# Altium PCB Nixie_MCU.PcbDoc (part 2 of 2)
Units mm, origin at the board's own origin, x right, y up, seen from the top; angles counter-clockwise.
Board outline 188 x 42 mm, 4 copper layers (Signal Layer 1, Layer 1, Layer 2, Bottom Layer), stack 1.466 mm thick; 180 components, 100 nets, 460 pads, 258 vias.
Unrouted connection lines stored in the file: 2.
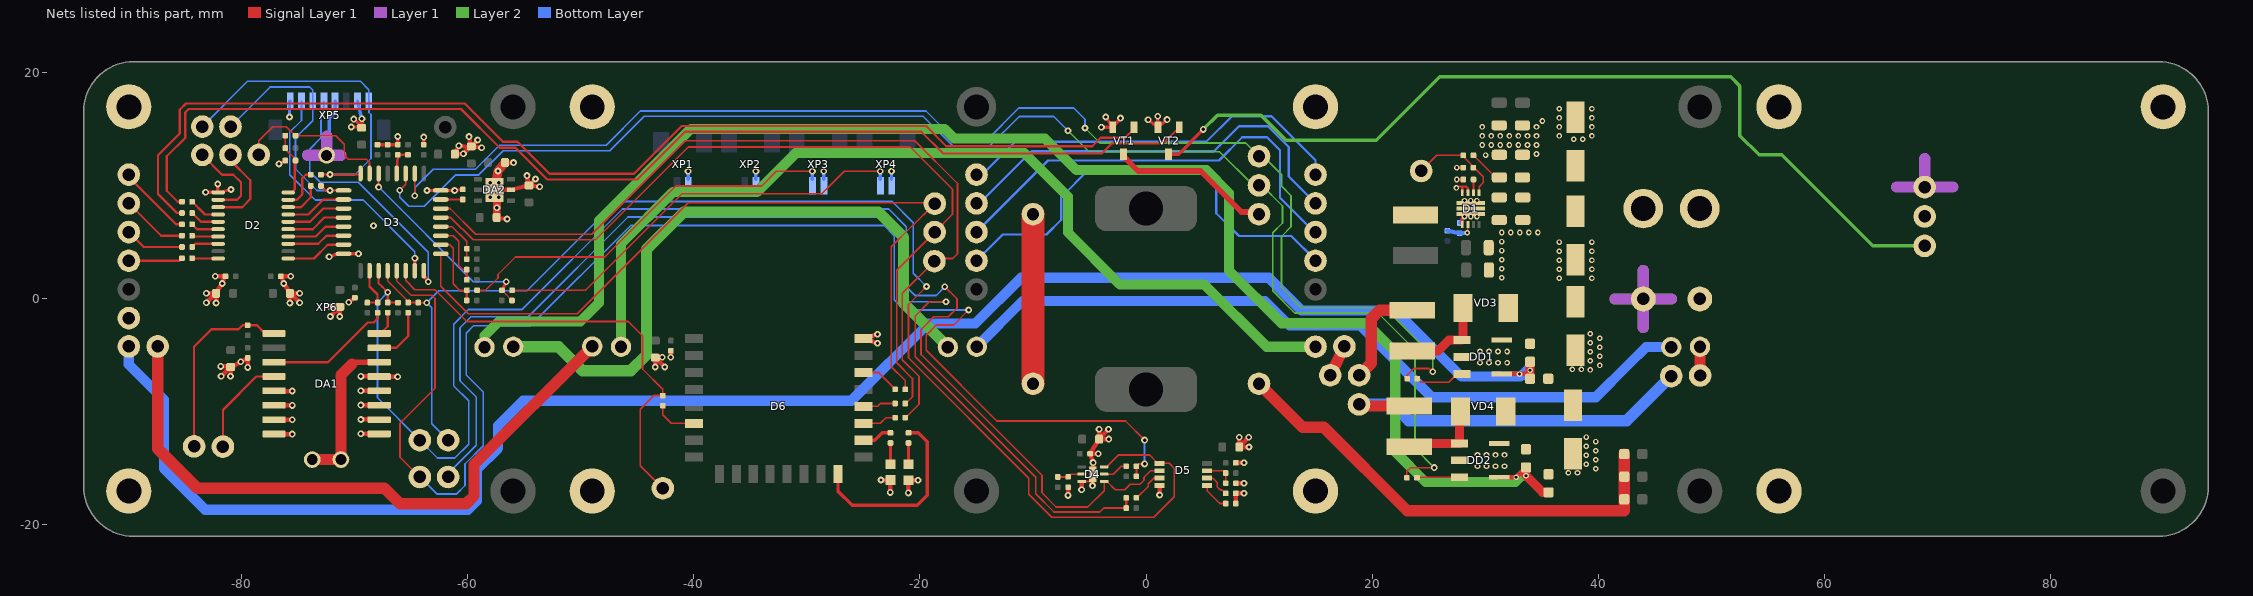
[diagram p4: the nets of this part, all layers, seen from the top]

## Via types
v1: diameter 0.6, hole 0.3, Signal Layer 1 to Bottom Layer, tented both sides, 153 vias
v2: diameter 0.5, hole 0.25, Signal Layer 1 to Bottom Layer, tented both sides, 101 vias
v3: diameter 0.6, hole 0.3, Signal Layer 1 to Bottom Layer, 4 vias

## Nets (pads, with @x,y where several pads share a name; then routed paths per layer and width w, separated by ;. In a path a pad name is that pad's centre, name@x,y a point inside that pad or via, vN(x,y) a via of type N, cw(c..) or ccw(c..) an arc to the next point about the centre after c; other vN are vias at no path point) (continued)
BTN_3: R38.1 XP3.1 | length 34.9
  Signal Layer 1 w0.15: R38.1@-59.189,0.766 -58.434,0.766 -57.341,1.859 -57.341,2.159 -55.783,3.717 -47.891,3.717 -41.607,10 -34,10 -32.701,11.299 v1(-29.515,11.299)
  Bottom Layer w0.3: XP3.1@-29.515,10.578 v1(-29.515,11.299)
BTN_4: R45.1 XP4.1 | length 37.7
  Signal Layer 1 w0.15: R45.1@-56.087,0.772 -55.228,0.772 -49.59,0.772 -41.05,9.311 -28.689,9.311 -26.701,11.299 v1(-23.515,11.299)
  Bottom Layer w0.3: XP4.1@-23.515,10.578 v1(-23.515,11.299)
DIMM_LED_1: D3.2 R5.1 XS41.1 | length 118.3
  Signal Layer 1 w0.15: v1(-64.708,9.13) -64.7,9.75 D3.2@-64.7,11.1 ; R5.1@23.1,-7.05 23.1,-6.75 23.7,-6.15 25.075,-6.15 v1(25.375,-6.45)
  Layer 2 w0.15: v1(-5.4,15.125) -4.075,13.8 8.825,13.8 XS41.1@10,12.625 10.375,12.625 12,11 12,9.958 12.828,9.129 12.828,6.377 11.983,5.532 11.983,0.984 13.751,-0.784 21.111,-0.784 25.375,-5.048 v1(25.375,-6.45)
  Bottom Layer w0.15: v1(-64.708,9.13) -64.708,9.842 -63.075,11.475 -59.325,11.475 -57.2,13.6 -47.761,13.6 -44.734,16.626 -19.471,16.626 -16.944,14.1 -14.05,14.1 -11.25,16.9 -6.4,16.9 -5.4,15.9 v1(-5.4,15.125)
DIMM_LED_2: D3.3 R57.1 XS62.1 | length 126.4
  Signal Layer 1 w0.15: v1(-66.025,9.625) -65.5,10.15 D3.3@-65.5,11.1 ; R57.1@23.075,-15.825 23.075,-15.25 23.4,-14.925 v1(25.5,-14.925)
  Layer 2 w0.15: v1(-6.9,14.875) -5.05,13.025 6.5,13.025 9.475,10.05 XS62.1@10,10.05 10.256,10.05 12.076,8.23 12.076,6.717 11.209,5.849 11.209,0.716 13.17,-1.245 20.53,-1.245 23.798,-4.513 23.798,-13.223 v1(25.5,-14.925)
  Bottom Layer w0.15: v1(-66.025,9.625) -66.025,9 -65.225,8.2 -63.85,8.2 -61.075,10.975 -59.025,10.975 -56.875,13.125 -47.45,13.125 -44.399,16.176 -19.726,16.176 -17.05,13.5 -13.875,13.5 -11.225,16.15 -8.175,16.15 v1(-6.9,14.875)
DIN: XS30.1 XS36.1 | length 35
  Bottom Layer w0.2: XS30.1@-15,11 -14.5,11 -11.6,13.9 5.325,13.9 7.6,16.175 11.094,16.175 15,12.269 XS36.1@15,11
DIN_3.3V: D2.5 D3.12 | length 5.3
  Signal Layer 1 w0.2: D2.5@-75.9,6.175 -73.725,6.175 -72.7,7.2 D3.12@-71,7.2
DIN_5V: R10.2 XS6.1 | length 6.7
  Signal Layer 1 w0.2: XS6.1@-90,11 -90,10.781 -85.819,6.6 R10.2@-85.3,6.6
EN_VCC3.3: D1.8 R1.1 R2.2 XS51.1 | length 8.5
  Signal Layer 1 w0.15: XS51.1@24.35,11.325 25.729,12.704 R2.2@28.073,12.704 28.073,12.602 29.85,10.825 29.85,10.31 29.477,9.937 D1.8@29.477,9.4
GND: C1.1 C2.1 C3.1 C4.1 C5.2 C6.2 C7.2 C8.1 C9.1 C10.1 C11.1 C12.1 C13.1 C14.1 C15.1 C16.1 C17.1 C18.1 C19.1 C20.1 C21.1 C22.1 C23.1 C24.1 C25.1 C26.1 C27.1 C28.1 C29.1 C30.1 C31.1 C32.1 C33.1 C34.1 C35.1 C36.1 C37.2 D1.3 D1.4 D1.10 D1.11 D2.11 D3.16 D3.32 D4.3 D4.7 D5.4 D6.24 DA1.5 DA1.6 DA1.7 DA1.8 DA1.9 DA1.10 DA1.11 DA1.12 DA1.13 DA2.2 DA2.7 DD1.2 DD2.2 pad.16@15,17 pad.16@15,-17 pad.16@44,8 pad.16@56,17 pad.16@56,-17 pad.16@-49,17 pad.16@-49,-17 pad.16@-90,17 pad.16@-90,-17 R1.2 R3.2 R6.1 R18.2 R28.1 R31.2 R32.2 R33.2 VD1.2 VD2.2 VT1.2 VT2.2 XP1.2 XP2.2 XP3.2 XP4.2 XP5.1 XP5.5 XP5.7 XP6.2 XS2.1 XS8.1 XS23.1 | length 138.3
  Signal Layer 1 w0.2: D4.3@-5.695,-16.15 -5.014,-16.15 D4.7@-4.729,-15.865 ; v2(27.464,9.828) 27.586,9.95 27.977,9.95 ; D1.11@27.977,9.4 27.977,9.95 ; D1.10@28.477,9.4 28.477,9.792 28.319,9.95 27.977,9.95
  Signal Layer 1 w0.25: v2(27.496,11.624) R1.2@28.07,11.624 ; v2(27.499,10.568) C3.1@28.073,10.568 ; D1.4@27.97,6.606 27.97,7.094 v2(28.177,7.3)
  Signal Layer 1 w0.3: v1(-83.206,9.437) D2.11@-82.485,9.437 ; v1(-82.134,10.171) -82.134,9.45 D2.11@-82.105,9.42 ; D2.11@-82.1,9.425 v1(-80.963,9.683) ; v1(-76.71,11.952) -76.25,12.19 R6.1@-76.15,12.25 ; v1(-72.277,3.729) D3.16@-71.5,4 ; D3.16@-70.4,4 v1(-69.679,4) ; v1(-70.313,15.21) C19.1@-69.592,15.21 ; v1(-70.089,15.913) C19.1@-69.391,15.304 ; v1(-69.378,15.94) C19.1@-69.313,15.202 ; C18.1@-68,13.65 C17.1@-67.1,13.65 C14.1@-66.379,13.65 ; C14.1@-66.2,13.65 v1(-66.2,14.371) ; C15.1@-63.907,13.648 v1(-63.896,14.325) ; v1(-63.621,9.6) D3.32@-62.9,9.6 ; D3.32@-61.9,9.6 v1(-61.179,9.6) R18.2@-60.456,9.703 ; v1(-3.943,15.197) VT1.2@-2.95,15.2 ; v1(-3.564,16.101) VT1.2@-2.95,15.2 ; v1(-2.26,16.002) VT1.2@-2.95,15.2 ; v1(0.185,15.859) VT2.2@1.05,15.2 ; v1(1.049,16.166) VT2.2@1.05,15.2 ; v1(1.867,15.866) VT2.2@1.05,15.2
  Signal Layer 1 w0.4: v1(-83.137,-0.333) -82.304,0.5 v1(-83.137,0.5) ; v1(-82.362,2) -81.529,2 v1(-81.737,1.368) C12.1@-82.275,0.5 v1(-82.275,-0.362) ; v1(-81.862,-5.971) C21.1@-81,-5.971 ; v1(-81.833,-6.833) -81,-6 v1(-81,-6.833) ; C21.1@-80.691,-5.909 v1(-80.088,-5.565) C20.1@-79.485,-5.222 v1(-79.485,-6.055) ; DA1.8@-76.365,-11.958 v1(-75.532,-11.958) ; DA1.7@-76.365,-10.688 v1(-75.532,-10.688) ; DA1.6@-76.365,-9.418 v1(-75.532,-9.418) ; DA1.5@-76.365,-8.148 v1(-75.532,-8.148) ; v1(-75.75,-0.362) C9.1@-75.75,0.5 v1(-76.288,1.368) -76.496,2 v1(-75.663,2) ; v1(-74.888,-0.333) -75.721,0.5 v1(-74.888,0.5) ; v1(-72.196,-0.695) C16.1@-71.334,-0.695 ; v1(-72.167,-1.557) -71.334,-0.724 v1(-71.334,-1.557) ; v1(-70.547,-0.285) C13.1@-69.994,0.109 ; v1(-69.468,-11.932) DA1.9@-68.635,-11.932 ; v1(-69.468,-10.662) DA1.10@-68.635,-10.662 ; v1(-69.468,-9.392) DA1.11@-68.635,-9.392 ; v1(-69.468,-8.122) DA1.12@-68.635,-8.122 ; v1(-69.468,-6.852) DA1.13@-68.635,-6.852 ; DA1.13@-67.055,-6.878 v1(-66.222,-6.878) ; C26.1@-61.178,12.82 -61.172,12.831 v1(-60.796,13.555) C30.1@-59.879,13.429 ; C26.1@-61.149,12.82 v1(-60.398,12.839) C30.1@-59.84,13.405 ; v1(-59.901,14.362) C30.1@-59.729,13.5 ; v1(-59.142,14.066) C30.1@-59.7,13.5 v1(-58.783,13.374) ; DA2.7@-57.647,9.642 DA2.2@-56.197,9.642 C27.1@-54.6,10.05 v1(-54.772,10.912) ; C28.1@-57.479,7.2 -57.479,7.201 -57.451,7.734 v1(-57.434,8.074) ; C28.1@-57.45,7.2 v1(-56.533,7.074) ; C29.1@-56.723,12.073 v1(-55.966,12.064) ; v1(-54.013,10.616) -54.571,10.05 v1(-53.654,9.924) ; v1(-43.416,-6.024) C31.1@-43.416,-5.19 ; v1(-42.808,-5.156) -43.382,-5.156 C31.1@-43.416,-5.19 ; v1(-42.583,-6.024) C31.1@-43.416,-5.19 ; v1(-42.047,-5.148) C32.1@-42.04,-4.579 ; v1(-23.753,-3.916) -24.993,-3.522 v1(-23.753,-3.127) ; v1(-23.444,-16.021) VD1.2@-22.61,-16.021 ; v1(-22.637,-17.12) VD1.2@-22.637,-16.287 ; v1(-21.023,-17.164) VD2.2@-21.023,-16.33 ; VD2.2@-21.011,-16.036 v1(-20.178,-16.036) ; v1(-6.898,-17.381) R28.1@-6.895,-16.646 ; v1(-5.698,-16.884) D4.3@-5.695,-16.232 ; v1(-4.732,-16.518) D4.7@-4.729,-15.865 ; D4.7@-4.681,-15.128 v1(-4.678,-14.476) C24.1@-4.95,-13.7 ; v1(-4.216,-13.703) C24.1@-4.95,-13.7 ; v1(-4.15,-11.538) -4.15,-12.371 v1(-3.317,-11.538) ; v1(-3.288,-12.4) C22.1@-4.15,-12.4 C24.1@-4.95,-13.7 ; v1(1.2,-17.35) D5.4@1.2,-16.627 ; R33.2@7.95,-18.1 R32.2@7.95,-17.377 ; R32.2@7.95,-17.2 v1(8.673,-17.2) ; R31.2@7.95,-16.3 v1(8.673,-16.3) ; C25.1@7.95,-14.5 v1(8.673,-14.5) ; C23.1@8.25,-13.1 v1(9.112,-13.1) ; v1(8.25,-12.238) 8.25,-13.071 v1(9.083,-12.238)
  Signal Layer 1 w0.7: C28.1@-57.45,7.2 -57.446,7.77 v1(-57.434,8.074) -57.439,9.004 -57.439,9.008 DA2.7@-57.438,9.067
  Signal Layer 1 w0.8: DA2.7@-57.647,9.642 -57.545,10.187 -57.519,10.325 v1(-57.333,11.32) C29.1@-56.723,12.073
  Layer 1 w1: -74.187,12.713 -74.184,12.71 XP6.2@-72.5,12.71 ; -72.5,14.394 XP6.2@-72.5,12.71 ; -71.249,12.71 XP6.2@-72.5,12.71 ; 41.5,0 XS2.1@44,0 ; 44,-2.5 XS2.1@44,0 ; 44,2.5 XS2.1@44,0 ; 46.5,0 XS2.1@44,0 ; 66.4,9.9 XS23.1@68.9,9.9 ; 68.9,12.4 XS23.1@68.9,9.9 ; 71.4,9.9 XS23.1@68.9,9.9
  Layer 2 w1: 41.5,0 XS2.1@44,0 ; 44,-2.5 XS2.1@44,0 ; 44,2.5 XS2.1@44,0 ; 46.5,0 XS2.1@44,0
  Bottom Layer w0.3: v1(-75.785,16.1) -75.785,17.441 XP5.1@-75.726,17.5 ; XP6.2@-72.5,12.71 -72.25,12.96 -72.25,15.971 -71.75,16.471 XP5.5@-71.75,17.5 ; XP5.7@-69.766,17.5 v1(-69.378,15.94) ; XP1.2@-40.515,10.578 v1(-40.515,11.299) ; XP2.2@-34.515,10.578 v1(-34.515,11.299) ; XP3.2@-28.515,10.578 v1(-28.515,11.299) ; XP4.2@-22.515,10.578 v1(-22.515,11.299) ; R3.2@27.75,6.725 v2(28.177,7.3)
  other v1: -68.354,6.477
  other v2: 37.376,-15.38 38.176,-15.38 39.8,-15.025 29.325,-14.8 30.125,-14.8 30.925,-14.8 31.725,-14.8 38.95,-14.625 39.8,-14.225 38.95,-13.825 29.325,-13.8 30.125,-13.8 30.925,-13.8 31.725,-13.8 39.8,-13.425 38.95,-13.025 39.8,-12.625 38.95,-12.225 39.3,-6.275 37.726,-6.23 38.526,-6.23 40.15,-5.875 29.55,-5.65 30.35,-5.65 31.15,-5.65 31.95,-5.65 39.3,-5.475 40.15,-5.075 39.3,-4.675 29.55,-4.65 30.35,-4.65 31.15,-4.65 31.95,-4.65 40.15,-4.275 39.3,-3.875 40.15,-3.475 39.3,-3.075 36.57,1.826 39.45,1.826 31.475,1.875 36.57,2.626 39.45,2.626 31.475,2.675 36.57,3.426 39.45,3.426 31.475,3.475 36.57,4.226 39.45,4.226 31.475,4.275 36.57,5.026 39.45,5.026 31.475,5.075 31.475,5.875 32.275,5.875 33.075,5.875 33.875,5.875 34.675,5.875 28.727,7.3 29.277,7.3 30.05,12.725 34.55,12.825 29.75,13.625 30.55,13.625 31.35,13.625 32.15,13.625 32.95,13.625 33.75,13.625 34.55,13.625 37.85,14.125 38.65,14.125 29.75,14.425 30.55,14.425 31.35,14.425 32.15,14.425 32.95,14.425 33.75,14.425 34.55,14.425 36.57,14.425 39.45,14.425 29.75,15.225 34.55,15.225 36.57,15.225 39.45,15.225 35.075,15.75 36.57,16.025 39.45,16.025 36.57,16.825 39.45,16.825
  other v3: -58.028,9.007 -57.266,9.007 -58.028,10.277 -57.266,10.277
I2C_SCL: D3.19 D4.4 D5.2 R13.2 R15.1 XS43.1 | length 128.6
  Signal Layer 1 w0.15: v1(-17.8,1.075) -16.715,-0.01 -16.715,-0.796 -17.503,-1.584 -18.779,-1.584 -19.91,-2.715 -19.91,-4.908 -9.205,-15.612 -9.205,-17.159 -7.958,-18.406 -5.156,-18.406 -3.705,-16.955 D4.4@-3.705,-16.15 -3.45,-16.15 -2.721,-16.879 -1.879,-16.879 -1.391,-16.391 -0.534,-16.391 -0.172,-16.029 -0.172,-15.772 0.4,-15.2 D5.2@1.2,-15.2
  Signal Layer 1 w0.2: D3.19@-67.9,2.5 -67.9,1.4 -67.583,1.083 -67.146,0.646 v1(-67.088,0.588) ; R15.1@-67.088,-0.314 v1(-67.088,0.588) ; R15.1@-67.013,-0.324 R13.2@-66.187,-0.324
  Bottom Layer w0.15: v1(-67.088,0.588) -67.942,-0.265 ccw(c-67.8,-0.406) -68,-0.406 -68,-8.75 XS43.1@-64.25,-12.5 -62.682,-14.068 -61.159,-14.068 -59.933,-12.842 -59.933,-9.017 -61.252,-7.698 -61.252,-2.227 -59.95,-0.925 -55.2,-0.925 -46.32,7.955 -22.762,7.955 -21.206,6.398 -21.206,1.073 -20.431,0.298 -18.577,0.298 v1(-17.8,1.075)
I2C_SDA: D3.20 D4.6 D5.1 R12.2 R16.1 XS42.1 | length 119.5
  Signal Layer 1 w0.15: D3.20@-67.1,2.5 -67.1,1.589 -65.334,-0.177 -65.287,-0.177 -65.141,-0.176 R16.1@-65.286,-0.318 R12.2@-64.389,-0.318 ; R12.2@-64.533,-0.343 v1(-63.636,-0.343) ; v1(-19.425,1.1) -21.011,-0.486 -21.011,-5.201 -10.362,-15.85 -10.362,-17.275 -8.33,-19.306 0.694,-19.306 2.5,-17.5 2.5,-15 2.05,-14.55 D5.1@1.2,-14.55 ; D4.6@-3.705,-14.85 -3.473,-14.85 -2.423,-13.8 0.308,-13.8 D5.1@0.978,-14.47
  Bottom Layer w0.15: XS42.1@-61.75,-12.5 -63.207,-11.043 -63.207,-0.771 v1(-63.636,-0.343) -62.568,0.725 -54.77,0.725 -46.876,8.619 -22.465,8.619 -20.603,6.757 -20.603,2.278 v1(-19.425,1.1)
I\N\T\\/SQW: D3.18 R11.2 R17.1 | length 4
  Signal Layer 1 w0.2: R11.2@-68.891,-0.32 -67.992,-0.32 R17.1@-67.988,-0.316 -67.988,0.388 -68.7,1.1 D3.18@-68.7,2.5
INS_EN_3.3V: D2.6 D3.11 | length 5.4
  Signal Layer 1 w0.2: D2.6@-75.9,6.825 -73.975,6.825 -72.8,8 D3.11@-71,8
INS_EN_5V: D2.15 R23.2 | length 2.6
  Signal Layer 1 w0.2: R23.2@-84.395,7.603 -83.618,6.825 D2.15@-82.1,6.825
INT_OPT: D3.21 R34.2 R36.1 XS44.1 | length 129.7
  Signal Layer 1 w0.15: D3.21@-66.3,2.5 -66.3,1.595 -65.037,0.332 -63.198,0.332 -62.905,0.038 -62.905,-7.905 -66,-11 -66,-14 XS44.1@-64.25,-15.75 ; v1(-15.7,-0.975) -17.025,-2.3 -18.55,-2.3 -19.45,-3.2 -19.45,-4.55 -13.2,-10.8 -1.809,-10.8 v1(-0.122,-12.487)
  Signal Layer 1 w0.2: R36.1@-0.85,-15.7 R34.2@-0.85,-14.8 -0.647,-14.597 v1(-0.123,-14.597)
  Bottom Layer w0.15: XS44.1@-64.25,-15.75 -62.75,-17.25 -61,-17.25 -60.25,-16.5 -60.25,-14.6 -58.644,-12.994 -58.644,-8.231 -60.15,-6.725 -60.15,-3.025 -59.5,-2.375 -54.479,-2.375 -45.602,6.502 -23.185,6.502 -22.282,5.599 -22.282,-0.068 -21.375,-0.975 v1(-15.7,-0.975)
  Bottom Layer w0.2: v1(-0.123,-14.597) v1@-0.123,-12.488
JDY_PWRC: D3.25 R50.1 XS47.1 | length 70.2
  Signal Layer 1 w0.15: D3.25@-62.4,4 -62.4,1.133 -59.957,-1.31 -50.31,-1.31 -40.489,8.511 -18.758,8.511 XS47.1@-18.686,8.438 -20.72,6.404 -20.746,6.404 -22.532,4.618 -22.532,-5.992 -21.306,-7.219 R50.1@-21.306,-7.994
JDY_STAT: D3.22 R49.1 XS48.1 | length 40.2
  Signal Layer 1 w0.15: D3.22@-65.5,2.5 -65.5,1.64 -64.687,0.827 -62.924,0.827 -62.621,0.524 -60.097,-2 -45.8,-2 -44.55,-3.25 -44.55,-6.2 -42.75,-8 R49.1@-42.75,-8.55 -43.55,-8.55 -44.75,-9.75 -44.75,-14.75 XS48.1@-42.75,-16.75
NetC3_2: C3.2 D1.9 | length 1.2
  Signal Layer 1 w0.2: C3.2@28.973,10.568 28.977,10.418 28.977,9.795 cw(c28.477,9.792) 28.977,9.792 D1.9@28.977,9.4
NetC14_2: C14.2 D3.4 R19.2 | length 2.6
  Signal Layer 1 w0.2: D3.4@-66.3,11.1 C14.2@-66.2,12.75 R19.2@-65.3,12.75
NetD1_2: D1.2 L1.1
NetD1_5: D1.5 R3.1 R4.2 | length 2.5
  Signal Layer 1 w0.15: v2(28.427,5.861) 28.468,6.375 D1.5@28.477,6.6
  Bottom Layer w0.4: R4.2@26.675,6.025 R3.1@27.75,5.825 v2(28.427,5.861)
NetD2_16: D2.16 R10.1 | length 2.5
  Signal Layer 1 w0.2: R10.1@-84.4,6.6 -83.975,6.175 D2.16@-82.1,6.175
NetD2_17: D2.17 R9.1 | length 2.3
  Signal Layer 1 w0.2: R9.1@-84.4,5.6 -84.325,5.525 D2.17@-82.1,5.525
NetD2_18: D2.18 R8.1 | length 2.4
  Signal Layer 1 w0.2: R8.1@-84.4,4.6 -84.125,4.875 D2.18@-82.1,4.875
NetD2_20: D2.20 R7.1 | length 2.3
  Signal Layer 1 w0.2: R7.1@-84.4,3.6 -84.375,3.575 D2.20@-82.1,3.575
NetD3_6: D3.6 R41.2 R45.2 | length 18.1
  Signal Layer 1 w0.15: R45.2@-56.987,0.772 -56.987,0.755 R41.2@-56.099,-0.132
  Signal Layer 1 w0.2: v1@-67.9,9.916 D3.6@-67.9,11.1
  Signal Layer 1 w0.3: R45.2@-56.987,0.772 -56.599,1.511 v1(-56.603,1.518)
  Bottom Layer w0.15: v1(-67.9,9.9) -59.518,1.518 v1(-56.603,1.518)
NetD3_7: D3.7 R46.2 XS46.1 | length 14.4
  Signal Layer 1 w0.15: XS46.1@-78.5,12.75 -78.5,14 -77.25,15.25 -76.056,15.25 R46.2@-75.258,14.453 ; R46.2@-75.25,14.453 -71.703,14.453 -70.943,13.693 -70.943,12.714 -70.59,12.361 -68.968,12.361 -68.7,12.093 D3.7@-68.7,11.1
NetD3_26: D3.26 R38.2 R42.2 | length 6.7
  Signal Layer 1 w0.15: D3.26@-62.4,4.8 -61.6,4.8 -61.3,4.5 -61.3,1.341 -60.711,0.753 R38.2@-60.102,0.753
  Signal Layer 1 w0.2: R42.2@-60.102,-0.132 R38.2@-60.102,0.753
NetD3_27: D3.27 R39.2 R43.2 | length 5.7
  Signal Layer 1 w0.15: D3.27@-62.4,5.6 -61.3,5.6 -60.8,5.1 -60.8,2.945 -60.455,2.6 R43.2@-60.1,2.6
  Signal Layer 1 w0.2: R43.2@-60.1,2.6 -60.094,2.594 R39.2@-60.094,1.688
NetD3_28: D3.28 R40.2 R44.2 | length 4.4
  Signal Layer 1 w0.15: D3.28@-62.4,6.4 -61.4,6.4 -60.102,5.102 R40.2@-60.102,3.519
NetD3_31: D3.31 R18.1 | length 2
  Signal Layer 1 w0.2: D3.31@-62.4,8.8 R18.1@-60.45,8.8
NetD4_2: D4.2 R28.2 R29.2 | length 2.2
  Signal Layer 1 w0.15: R29.2@-7.8,-15.75 -7.796,-15.746 R28.2@-6.895,-15.746 -6.648,-15.5 D4.2@-5.695,-15.5
NetD4_5: D4.5 R34.1 | length 2.2
  Signal Layer 1 w0.15: D4.5@-3.705,-15.5 -2.9,-15.5 -2.2,-14.8 R34.1@-1.75,-14.8
NetD5_3: D5.3 R35.1 | length 2.9
  Signal Layer 1 w0.15: R35.1@-0.85,-17.6 -0.818,-17.6 0.195,-16.587 0.195,-16.337 0.682,-15.85 D5.3@1.2,-15.85
NetD5_5: D5.5 R33.1 | length 2.6
  Signal Layer 1 w0.15: D5.5@5.39,-16.5 5.416,-16.526 5.416,-16.991 6.525,-18.1 R33.1@7.05,-18.1
NetD5_6: D5.6 R32.1 | length 2.5
  Signal Layer 1 w0.15: D5.6@5.393,-15.853 5.928,-15.853 6.311,-16.236 6.311,-16.638 6.569,-16.896 6.737,-16.896 ccw(c6.9,-16.45) 6.751,-16.901 R32.1@7.05,-17.2
NetD5_7: D5.7 R30.1 R31.1 | length 2.6
  Signal Layer 1 w0.15: D5.7@5.39,-15.2 6.85,-15.2 R30.1@7.05,-15.4 R31.1@7.05,-16.3
NetD6_6: D6.6 R49.2 | length 3.9
  Signal Layer 1 w0.15: R49.2@-42.75,-9.45 -42.75,-10.25 -42,-11 D6.6@-40,-11
NetD6_16: D6.16 R51.2 | length 17
  Signal Layer 1 w0.3: D6.16@-27.25,-15.5 -27.25,-17 -26,-18.25 -20.25,-18.25 -19.355,-17.355 -19.355,-12.645 -20.15,-11.85 R51.2@-21.011,-11.85
NetD6_18: D6.18 R52.2 | length 2.7
  Signal Layer 1 w0.3: D6.18@-25,-12.5 -24,-12.5 -23.35,-11.85 R52.2@-22.61,-11.85
NetD6_19: D6.19 R47.2 | length 3
  Signal Layer 1 w0.15: D6.19@-25,-11 -23.5,-11 -23,-10.5 R47.2@-22.2,-10.5
NetD6_20: D6.20 R48.2 | length 2.9
  Signal Layer 1 w0.15: D6.20@-25,-9.5 -23.75,-9.5 -23.5,-9.25 R48.2@-22.2,-9.25
NetD6_22: D6.22 R50.2 | length 3.4
  Signal Layer 1 w0.15: D6.22@-25,-6.5 -23.7,-6.5 R50.2@-22.2,-8
NetDA1_1: DA1.1 R14.2 XS21.1 | length 17
  Signal Layer 1 w0.2: XS21.1@-84.223,-13.045 -84.223,-4.223 -82.682,-2.682 -80.292,-2.682 -79.932,-2.322 R14.2@-79.485,-2.322 ; R14.2@-79.485,-2.332 -78.668,-2.332 -77.945,-3.055 DA1.1@-77.155,-3.055
NetDA1_3: DA1.3 R17.2 | length 11.3
  Signal Layer 1 w0.2: DA1.3@-77.155,-5.595 -72.383,-5.595 -68.864,-2.076 -68.326,-2.076 -67.988,-1.738 R17.2@-67.988,-1.216
NetDA1_4: DA1.4 XS20.1 | length 9
  Signal Layer 1 w0.2: XS20.1@-81.673,-13.067 -81.673,-9.817 -78.72,-6.865 DA1.4@-77.155,-6.865
NetDA1_14: DA1.14 XP6.1 | length 13.9
  Signal Layer 1 w0.5: -70.25,-5.75 -70.095,-5.595 DA1.14@-67.845,-5.595
  Signal Layer 1 w1: XP6.1@-73.77,-14.21 XP6.1@-71.23,-14.21 -71.23,-6.73 -70.25,-5.75
NetDA1_15: DA1.15 R16.2 | length 5.1
  Signal Layer 1 w0.2: DA1.15@-67.845,-4.325 -66.325,-4.325 -65.286,-3.286 R16.2@-65.286,-1.218
NetDA1_16: DA1.16 R15.2 | length 2.2
  Signal Layer 1 w0.2: DA1.16@-67.845,-3.055 -67.722,-3.055 -67.088,-2.421 R15.2@-67.088,-1.214
NetDD1_1: DD1.1 L2.1 VD3.1 | length 7.7
  Signal Layer 1 w0.8: L2.1@23.55,-4.6 25.85,-4.6 26.825,-3.625 DD1.1@27.975,-3.625 28.05,-3.55 VD3.1@28.05,-0.8
NetDD1_3: DD1.3 R5.2 | length 4.4
  Signal Layer 1 w0.15: R5.2@24,-7.05 24.325,-7.375 26.775,-7.375 27.525,-6.625 DD1.3@27.975,-6.625
NetDD1_4: DD1.4 R53.1 R54.1 XS15.1 | length 153.8
  Signal Layer 1 w0.4: DD1.4@31.48,-6.625 33.55,-6.625 R54.1@33.989,-7.063
  Signal Layer 1 w0.8: R54.1@33.989,-7.063 v2(33.989,-6.312) R53.1@33.988,-5.561
  Bottom Layer w0.9: XS15.1@-90,-4.2 -90,-5.8 -86.9,-8.9 -86.9,-15 -83.25,-18.65 -60,-18.65 -59.2,-17.85 -59.2,-15.075 -57.325,-13.2 -57.325,-11.2 -55.125,-9 -26.075,-9 -19.25,-2.175 -15.094,-2.175 -11.039,1.88 10.876,1.88 13.786,-1.03 22.067,-1.03 27.912,-6.875 33.15,-6.875 v2@33.851,-6.174
  other v2: 33.05,-6.65
NetDD2_1: DD2.1 L3.1 VD4.1 | length 7.4
  Signal Layer 1 w0.8: L3.1@23.3,-13.075 23.6,-12.775 DD2.1@27.75,-12.775 27.75,-10.025 VD4.1@27.825,-9.95
NetDD2_3: DD2.3 R57.2 | length 3.8
  Signal Layer 1 w0.15: R57.2@23.975,-15.825 24.025,-15.775 DD2.3@27.75,-15.775
NetDD2_4: DD2.4 R55.1 R56.1 XS55.1 | length 133.3
  Signal Layer 1 w0.4: DD2.4@31.255,-15.775 v2(32.75,-15.775) R55.1@33.625,-14.9
  Signal Layer 1 w0.8: R55.1@33.625,-14.9 v2(33.625,-15.64) 35.096,-17.111 R56.1@35.613,-17.111
  Layer 2 w0.9: XS55.1@-58.532,-4.262 -58.532,-3.257 -57.275,-2 -50.05,-2 -48.4,-0.35 -48.4,6.92 -40.27,15.05 -17.825,15.05 -16.975,14.2 -8.95,14.2 -6.15,11.4 5.325,11.4 7.35,9.375 7.35,2.5 11.997,-2.147 19.497,-2.147 22.05,-4.7 22.05,-13.525 24.725,-16.2 32.7,-16.2 33.425,-15.475
NetL2_2: L2.2 XS14.1 | length 9.4
  Signal Layer 1 w1: XS14.1@18.855,-6.753 19.925,-5.683 19.925,-1.75 20.675,-1 L2.2@23.55,-1
NetL3_2: L3.2 XS35.1 XS54.1 | length 34.4
  Signal Layer 1 w1: XS35.1@18.85,-9.325 19,-9.475 L3.2@23.3,-9.475
  Bottom Layer w1: XS35.1@18.85,-9.325 21.785,-9.325 23.227,-10.767 42.533,-10.767 XS54.1@46.475,-6.825
NetR20_1: R20.1 R21.1 R22.1 XS16.1 | length 42
  Signal Layer 1 w1: XS16.1@10,-7.5 13.85,-11.35 15.725,-11.35 23.102,-18.727 42.313,-18.727 R20.1@42.313,-17.727 R21.1@42.313,-15.727 R22.1@42.313,-13.727
NetR23_1: R23.1 VT1.1 | length 101.6
  Signal Layer 1 w0.2: R23.1@-85.295,7.603 -85.73,7.603 -87.414,9.286 -87.414,12.72 -85.5,14.634 -85.5,16.75 -84.95,17.3 -60.285,17.3 -56.885,13.901 -55.601,13.901 -52.769,11.069 -45.298,11.069 -41.067,15.3 -19.442,15.3 -17.664,13.522 -4.745,13.522 -4,14.267 -1.854,14.267 -1.05,15.07 VT1.1@-1.05,15.2
NetR24_1: R24.1 VT2.1 | length 103.5
  Signal Layer 1 w0.2: R24.1@-85.297,8.606 -85.676,8.606 -86.634,9.564 -86.634,12.616 -85,14.25 -85,16.5 -84.7,16.8 -82.081,16.8 -60.613,16.8 -57.189,13.376 -55.783,13.376 -55.054,12.646 ; -55.004,12.596 -52.976,10.569 -45.017,10.569 -40.786,14.8 -19.881,14.8 -17.946,12.864 -3.912,12.864 -3.027,13.75 1.5,13.75 VT2.1@2.95,15.2
NetR35_2: R35.2 R37.1 XS45.1 | length 101.4
  Signal Layer 1 w0.15: v1(-17.7,-0.25) -19.17,-0.25 -20.426,-1.506 -20.426,-5.099 -9.75,-15.776 -9.75,-17.25 -8.144,-18.856 -4.106,-18.856 -3.75,-18.5 R37.1@-1.75,-18.5
  Signal Layer 1 w0.2: R37.1@-1.75,-18.5 R35.2@-1.75,-17.6
  Bottom Layer w0.15: XS45.1@-61.75,-15.75 -61.75,-15.431 -59.253,-12.933 -59.253,-8.672 -60.7,-7.225 -60.7,-2.55 -59.725,-1.575 -54.652,-1.575 -45.827,7.249 -22.939,7.249 -21.728,6.038 -21.728,0.451 -21.027,-0.25 v1(-17.7,-0.25)
NetR51_1: R51.1 VD2.1 | length 1.9
  Signal Layer 1 w0.3: VD2.1@-21.011,-14.636 R51.1@-21.011,-12.75
NetR52_1: R52.1 VD1.1 | length 1.9
  Signal Layer 1 w0.3: VD1.1@-22.61,-14.621 R52.1@-22.61,-12.75
NetVT1_3: VT1.3 XS19.1 | length 14.3
  Signal Layer 1 w0.5: VT1.3@-2,12.8 -2,12.63 -0.695,11.325 4.825,11.325 8.45,7.7 9.8,7.7 XS19.1@10,7.5
NetVT2_3: VT2.3 XS24.1 | length 80.3
  Signal Layer 1 w0.3: VT2.3@2,12.8 2.88,12.801 v1(5.075,15)
  Layer 2 w0.3: v1(5.075,15) 6.325,16.25 10.175,16.25 12.389,14.036 20.368,14.036 25.988,19.656 51.731,19.656 52.546,18.841 52.546,14.454 54.25,12.75 56.25,12.75 64.3,4.7 XS24.1@68.9,4.7
NetXS10_1: XS10.1 XS11.1 | length 56.9
  Signal Layer 1 w1: XS10.1@-87.445,-4.203 -87.445,-13.255 -83.95,-16.75 -67.375,-16.75 -66,-18.125 -60.15,-18.125 -59.45,-17.425 -59.45,-14.65 XS11.1@-49,-4.2
NetXS12_1: XS12.1 XS13.1 | length 82.8
  Layer 2 w0.9: XS12.1@-46.45,-4.225 -46.45,4.867 -41.865,9.452 -34.448,9.452 -31,12.9 -10.75,12.9 -6.9,9.05 -6.9,5.875 -2.309,1.284 5.166,1.284 10.675,-4.225 XS13.1@15,-4.225
NetXS17_1: XS17.1 XS18.1 | length 15
  Signal Layer 1 w2: XS17.1@-10,-7.5 XS18.1@-10,7.5
NetXS52_1: XS52.1 XS53.1 | length 2.9
  Signal Layer 1 w1: XS53.1@16.3,-6.75 XS52.1@17.555,-4.203 XS52.1@17.525,-4.233
NetXS56_1: XS56.1 XS57.1 | length 59
  Layer 2 w1: XS56.1@-55.98,-4.231 -51.969,-4.231 -49.85,-6.35 -45.6,-6.35 -44.2,-4.95 -44.2,4.392 -40.892,7.7 -23.675,7.7 -21.45,5.475 -21.45,-0.344 XS57.1@-17.532,-4.262
NetXS58_1: XS58.1 XS59.1 | length 68.5
  Bottom Layer w0.9: XS58.1@-14.98,-4.231 -10.925,-0.176 10.517,-0.176 12.693,-2.352 18.929,-2.352 25.282,-8.705 39.791,-8.705 42.692,-5.804 44.234,-4.262 XS59.1@46.468,-4.262
NetXS60_1: XS60.1 XS61.1 | length 2.5
  Signal Layer 1 w1: XS60.1@49.02,-4.231 49.02,-6.77 XS61.1@49.025,-6.775
OE: XS31.1 XS37.1 | length 37.2
  Bottom Layer w0.2: XS31.1@-15,8.46 -14.727,8.46 -10.124,13.064 6.014,13.064 8.225,15.275 10.797,15.275 12.625,13.447 12.625,10.835 XS37.1@15,8.46
OE_3.3V: D2.4 D3.13 | length 5.3
  Signal Layer 1 w0.2: D2.4@-75.9,5.525 -73.456,5.525 -72.581,6.4 D3.13@-71,6.4
OE_5V: R9.2 XS5.1 | length 5.9
  Signal Layer 1 w0.2: XS5.1@-89.96,8.5 XS5.1@-90,8.46 -87.14,5.6 R9.2@-85.3,5.6
PA2_3.3V: D2.9 R25.2 | length 3.8
  Signal Layer 1 w0.2: D2.9@-75.9,8.775 -75.125,8.775 -74.65,9.25 -74.65,10.7 -74.35,11 R25.2@-73.9,11
PA2_5V: D2.12 XS26.1 | length 7.8
  Signal Layer 1 w0.2: XS26.1@-83.5,12.75 -81.75,11 -80.75,11 -80.073,10.323 -80.073,9.127 -80.425,8.775 D2.12@-82.1,8.775
PA3_3.3V: D2.8 R26.2 | length 3.4
  Signal Layer 1 w0.2: D2.8@-75.9,8.125 -74.775,8.125 -73.9,9 R26.2@-73.9,10
PA3_5V: D2.13 XS25.1 | length 7.8
  Signal Layer 1 w0.2: D2.13@-82.1,8.125 -79.975,8.125 -79.25,8.85 -79.25,10.5 -81,12.25 XS25.1@-81,12.75
RCK: XS32.1 XS38.1 | length 39.7
  Bottom Layer w0.2: XS32.1@-15,5.92 -8.665,12.255 6.455,12.255 8.505,14.305 10.698,14.305 11.85,13.153 11.85,8.95 14.88,5.92 XS38.1@15,5.92 XS38.1@15,6.176
RCK_3.3V: D2.3 D3.14 | length 5.2
  Signal Layer 1 w0.2: D2.3@-75.9,4.875 -73.23,4.875 -72.505,5.6 D3.14@-71,5.6
RCK_5V: R8.2 XS4.1 | length 5.2
  Signal Layer 1 w0.2: XS4.1@-90,5.92 -88.68,4.6 R8.2@-85.3,4.6
SCK: XS33.1 XS39.1 | length 39.3
  Bottom Layer w0.2: XS33.1@-15,3.38 -12.68,5.7 -8.8,5.7 -7.5,7 -7.5,9 -5.1,11.4 4.8,11.4 6.225,9.975 6.225,7.575 8.225,5.575 12.861,5.575 15,3.436 XS39.1@15,3.38
SCK_3.3V: D2.1 D3.15 | length 5.4
  Signal Layer 1 w0.2: D2.1@-75.9,3.575 -73.625,3.575 -72.4,4.8 D3.15@-71,4.8
SCK_5V: R7.2 XS3.1 | length 4.8
  Signal Layer 1 w0.2: XS3.1@-90,3.38 -85.52,3.38 R7.2@-85.3,3.6
SHDN_170V_3.3V: D2.7 D3.10 | length 5.4
  Signal Layer 1 w0.2: D2.7@-75.9,7.475 -74.125,7.475 -72.8,8.8 D3.10@-71,8.8
SHDN_170V_5V: D2.14 R24.2 | length 2.8
  Signal Layer 1 w0.2: R24.2@-84.397,8.606 -84.043,8.253 -84.038,8.253 -83.745,7.96 -83.745,7.955 -83.265,7.475 D2.14@-82.1,7.475
SWCLK: D3.24 XP5.4 | length 23.6
  Signal Layer 1 w0.3: D3.24@-63.91,2.122 v1(-63.498,1.519)
  Bottom Layer w0.15: XP5.4@-72.742,17.5 -72.742,16.508 -73,16.25 -73,14.25 -74,13.25 -74,11.25 -73.066,10.316 -69.697,10.316 -63.498,4.117 v1(-63.498,1.519)
SWDIO: D3.23 XP5.2 | length 22.1
  Signal Layer 1 w0.3: D3.23@-64.69,2.878 v1(-64.69,3.599)
  Bottom Layer w0.15: XP5.2@-74.726,17.5 -74.726,15.79 -75.75,14.766 -75.75,11 -73.5,8.75 -69.25,8.75 -64.69,4.19 v1(-64.69,3.599)
TXS_OE: D2.10 R6.2 R27.1 R46.1 | length 5.8
  Signal Layer 1 w0.15: R46.1@-76.15,14.453 R27.1@-76.15,13.352 -76.15,13.258 -75.25,12.358 R6.2@-75.25,12.25
  Signal Layer 1 w0.2: D2.10@-75.9,9.425 -75.575,9.425 -75.318,9.682 R6.2@-75.318,12.25
UART1_RX: D3.9 R26.1 XP5.3 XS28.1 | length 22.4
  Signal Layer 1 w0.2: R26.1@-73,10 -72.6,9.6 D3.9@-71,9.6
  Bottom Layer w0.15: XS28.1@-81,15.25 -77.5,18.75 -74,18.75 -73.734,18.484 XP5.3@-73.734,17.5 -73.734,15.766 -75.25,14.25 -75.25,11.5 -73.35,9.6 v1(-72.2,9.6)
UART1_TX: D3.8 R25.1 XP5.8 XS27.1 | length 30.6
  Signal Layer 1 w0.2: R25.1@-73,11 -72.85,11.015 v1(-72.2,11.015) ; v1@-72.2,11.017 -69.583,11.017 D3.8@-69.5,11.1
  Bottom Layer w0.15: XS27.1@-83.5,15.25 -79.5,19.25 -69.5,19.25 -68.774,18.524 XP5.8@-68.774,17.5 -68.75,17.476 -68.75,16.5 -68.575,16.325 -68.575,12.425 -69.985,11.015 v1(-72.2,11.015)
UART2_RX: D3.30 R47.1 XS50.1 | length 76.3
  Signal Layer 1 w0.15: D3.30@-62.4,8 -61.58,8 -59.308,5.728 -49.043,5.728 -40.77,14 -20.461,14 -16.676,10.215 -16.676,4.004 -17.1,3.58 -18.478,3.58 XS50.1@-18.718,3.34 -21.557,0.501 -21.557,-5.376 -20.085,-6.848 -20.085,-9.311 -21.275,-10.5 R47.1@-21.3,-10.5
UART2_TX: D3.29 R48.1 XS49.1 | length 72.9
  Signal Layer 1 w0.15: D3.29@-62.4,7.2 -61.509,7.2 -59.536,5.227 -48.712,5.227 -40.486,13.453 -20.881,13.453 -17.126,9.698 -17.126,7.492 XS49.1@-18.706,5.913 -18.706,5.896 -22.054,2.548 -22.054,-5.659 -20.666,-7.047 -20.666,-8.657 -21.26,-9.25 R48.1@-21.3,-9.25
VIN: C1.2 C2.2 C5.1 C6.1 C7.1 C33.2 C34.2 C37.1 D1.1 DD1.5 DD2.5 pad.16@49,8 pad.16@90,17 R2.1 R53.2 R54.2 R55.2 R56.2 VD3.2 VD4.2 XS1.1 XS22.1 | length 3.1
  Signal Layer 1 w0.15: R2.1@28.973,12.704 30.923,10.755 C33.2@31.267,10.755
  other v2: 28.177,8.7 28.727,8.7 29.277,8.7
pads on no net: D1.7 D2. D3. D5. D6.2 D6.3 D6.4 D6.5 D6.7 D6.8 D6.9 D6.10 D6.11 D6.12 D6.13 D6.14 D6.15 D6.17 D6.21 D6.23 VD3. VD4. VT1. VT2. XP1.K1 XP1.K2 XP2.K1 XP2.K2 XP3.K1 XP3.K2 XP4.K1 XP4.K2 XP5.SH1 XP5.SH2

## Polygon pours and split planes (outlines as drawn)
+3.3V on Layer 2 "NONET_L-01_P-001" (solid, remove dead copper, pour order 6): -60.75,17.5 -71.5,17.5 -75.25,13.75 -75.25,10 -78.75,6.5 -80.75,6.5 -84.25,3 -84.25,-4.25 -83.599,-4.901 -78,-4.901 -78,-5.679 -69.179,-14.5 -12.5,-14.5 -10,-17 -7.5,-19.5 9.5,-19.5 11.25,-17.75 11.25,-13 9.5,-11.25 -1.75,-11.25 -2.25,-10.75 -4,-10.75 -5.75,-9 -5.75,-4.75 -7.695,-2.805 -50.445,-2.805 -58.25,5 -59.5,5 -60.5,6 -60.5,17.222
GND on Layer 2 "NONET_L-01_P-001" (solid, pour order 31): 27.583,7.941 27.575,7.933 27.575,6.539 28.307,5.807 28.307,3.378 26.359,1.43 26.359,-13.756 27.77,-15.167 32.003,-15.167 32.866,-14.304 34.731,-14.304 40.387,-19.96 90.445,-19.96 93.008,-17.396 93,-17.388 93,18 91,20 54.941,20 53.541,18.599 53.541,15.184 54.888,13.837 56.937,13.837 64.49,6.284 70.052,6.284 71.087,5.25 71.087,3.864 70.169,2.947 64.053,2.947 57,10 29.639,10 27.576,7.938
+5V on Layer 2 "NONET_L-01_P-001" (solid, pour order 30): 13.856,1.632 13.856,0.388 14.427,-0.184 23.645,-0.184 27.82,3.991 27.82,5.504 27.107,6.218 27.107,8.057 30.049,11 47.08,11 51.416,15.336 51.416,17.639 50.128,18.927 26.927,18.927 17,9 17,3 15.899,1.899 14.125,1.899 13.852,1.626
+5V on Layer 2 "NONET_L-01_P-001" (solid, pour order 7): -55.28,19.452 -55.327,19.5 -57.25,19.5 -58.5,18.25 -59.938,16.812 -59.938,6.688 -59.25,6 -53.5,6 -51.5,8 -51.5,14 -52.5,15 -52.5,18.25 -53.75,19.5 -55.5,19.5
VIN on Bottom Layer "NONET_L-01_P-001" (solid, pour order 16): 47,11 47,-0.5 48,-1.5 80.5,-1.5 92.5,10.5 92.5,18 91,19.5 65.5,19.5 58.5,12.5 48.5,12.5
GND on Signal Layer 1 "NONET_L-01_P-001" (solid, pour order 27): 29.6,1.575 40.75,1.575 45.975,6.8 45.975,9.05 45,10.025 43.125,10.025 41.525,8.425 41.525,6.975 40.075,5.525 36.275,5.525 33.825,7.975 30.825,7.975 30.277,7.427 30.277,5.527 29.35,4.6 29.35,1.825
VIN on Signal Layer 1 "Signal Layer 1-VIN" (solid, pour order 25): 30.375,-12.975 30.4,-13 32.475,-13 33.375,-13.9 34.25,-13.9 34.825,-14.475 34.825,-15.725 35.1,-16 36.025,-16 36.25,-15.775 36.25,-11.875 36.975,-11.15 50.125,-11.15 51.25,-10.025 51.25,-3.325 51.225,-3.325 51.225,10.15 48.225,13.15 36.4,13.15 34.55,11.3 30.75,11.3 30.275,10.825 30.275,8.575 30.525,8.325 34.2,8.325 36.5,6.025 39.7,6.025 40.725,7.05 40.725,8.625 42.675,10.575 45.55,10.575 46.525,9.6 46.525,6.55 42.875,2.9 42.825,2.9 41.075,1.15 30.85,1.15 30.225,0.525 30.225,-3.45 30.6,-3.825 32.8,-3.825 33.6,-4.625 34.5,-4.625 34.95,-5.075 34.95,-7.5 33.95,-8.5 31.05,-8.5 30.375,-9.175
GND on Signal Layer 1 "NONET_L-01_P-001" (solid, pour order 29): 43.25,14.3 40.025,17.525 36,17.525 34.4,15.925 29.225,15.925 28.6,15.3 28.6,14.075 29.7,12.975 29.7,12.625 30.2,12.125 34.525,12.125 36.05,13.65 43.1,13.65 43.25,13.8
+5V on Signal Layer 1 "NONET_L-01_P-001" (solid, pour order 28): 28.998,5.243 29,5.241 29,1.875 28.575,1.45 20.8,1.45 17.775,-1.575 14.5,-1.575 13.625,-0.7 13.625,1.275 14.225,1.875 16.1,1.875 16.95,2.725 16.95,14.5 21.925,19.475 50.25,19.475 51.225,18.5 51.225,15.475 49.5,13.75 44.65,13.75 40.35,18.05 35.75,18.05 34.3,16.6 29.3,16.6 26.325,13.625 23.8,13.625 20.775,10.6 20.775,6.35 22.175,4.95 26.775,4.95 27.068,5.243
GND on Layer 1 "NONET_L-01_P-001" (solid, pour order 5): -93.127,-16.586 ccw(c-89.586,-16.586) -89.586,-20.127 89.586,-20.127 ccw(c89.586,-16.586) 93.127,-16.586 93.127,16.586 ccw(c89.586,16.586) 89.586,20.127 56.414,20.127 -89.586,20.127 ccw(c-89.586,16.586) -93.127,16.586

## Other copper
Signal Layer 1:
  region net NetD1_2: 21.798,8.35 27.177,8.35 27.352,8.175 27.852,8.175 27.852,7.825 27.332,7.825 26.182,6.675 21.798,6.675
  region net GND: 37.475,-11.775 36.975,-12.275 36.975,-15.425 37.325,-15.775 39.625,-15.775 40.25,-15.15 40.25,-12.55 39.475,-11.775 39.125,-11.775
  region net GND: 37.7,-2.625 37.2,-3.125 37.2,-6.275 37.55,-6.625 39.85,-6.625 40.475,-6 40.475,-3.4 39.7,-2.625 39.35,-2.625
  pour cut-out: 36.7,-6.5 37.125,-6.925 41,-6.925 41,-3.325 39.875,-2.2 37.3,-2.2 36.7,-2.8
  region net VIN: 27.477,8.85 27.577,8.95 29.827,8.95 30.277,9.4 30.277,9.85 32.027,9.85 32.027,8.325 28.027,8.325 28.027,8.45 27.477,8.45
  region net GND: 27.477,7.15 27.577,7.05 29.827,7.05 30.277,6.6 30.277,6.15 32.027,6.15 32.027,7.675 28.027,7.675 28.027,7.55 27.477,7.55
Layer 1:
  pour cut-out: 42.197,0 ccw(c44,0) 44,-1.803 ccw(c44,0) 45.803,0 ccw(c44,0) 44,1.803 ccw(c44,0)
  pour cut-out: 67.626,9.9 ccw(c68.9,9.9) 68.9,8.626 ccw(c68.9,9.9) 70.174,9.9 ccw(c68.9,9.9) 68.9,11.174 ccw(c68.9,9.9)
  pour cut-out: -73.774,12.71 ccw(c-72.5,12.71) -72.5,11.436 ccw(c-72.5,12.71) -71.226,12.71 ccw(c-72.5,12.71) -72.5,13.984 ccw(c-72.5,12.71)
  pour cut-out: -59.034,-17 ccw(c-56,-17) -56,-20.034 ccw(c-56,-17) -52.966,-17 ccw(c-56,-17) -56,-13.966 ccw(c-56,-17)
  pour cut-out: 86.966,-17 ccw(c90,-17) 90,-20.034 ccw(c90,-17) 93.034,-17 ccw(c90,-17) 90,-13.966 ccw(c90,-17)
  pour cut-out: 45.966,-17 ccw(c49,-17) 49,-20.034 ccw(c49,-17) 52.034,-17 ccw(c49,-17) 49,-13.966 ccw(c49,-17)
  pour cut-out: -18.034,-17 ccw(c-15,-17) -15,-20.034 ccw(c-15,-17) -11.966,-17 ccw(c-15,-17) -15,-13.966 ccw(c-15,-17)
Layer 2:
  pour cut-out: 42.197,0 ccw(c44,0) 44,-1.803 ccw(c44,0) 45.803,0 ccw(c44,0) 44,1.803 ccw(c44,0)
  pour cut-out: 86.966,-17 ccw(c90,-17) 90,-20.034 ccw(c90,-17) 93.034,-17 ccw(c90,-17) 90,-13.966 ccw(c90,-17)
  pour cut-out: 45.966,-17 ccw(c49,-17) 49,-20.034 ccw(c49,-17) 52.034,-17 ccw(c49,-17) 49,-13.966 ccw(c49,-17)
  pour cut-out: -18.034,-17 ccw(c-15,-17) -15,-20.034 ccw(c-15,-17) -11.966,-17 ccw(c-15,-17) -15,-13.966 ccw(c-15,-17)
  pour cut-out: -59.034,-17 ccw(c-56,-17) -56,-20.034 ccw(c-56,-17) -52.966,-17 ccw(c-56,-17) -56,-13.966 ccw(c-56,-17)

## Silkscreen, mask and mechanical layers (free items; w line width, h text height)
Top Overlay:
  drawing of 51 lines, arcs and shapes, not listed
  text "U1_RX" at -81.909,17.353 h1.2
  text "U1_TX" at -85.784,17.328 h1.2
  text "+3.3V" at -63.63,17.154 h1.2
  text "DM_LED1" at 6.123,16.09 h1.2
  text "DM_LED2" at 6.123,14.64 h1.2
  text "VCC_5V" at -58.549,13.172 h1.2
  text "VCC_5V" at -17.554,13.015 h1.2
  text "VCC_5V" at 46.446,13.025 h1.2
  text "VIN" at 87.446,13.017 h1.2
  text "GND" at -92.549,13 h1.2
  text "GND" at -51.549,13.01 h1.2
  text "GND" at 53.451,12.99 h1.2
  text "GND" at 12.451,12.984 h1.2
  text "DIN" at -88.429,10.47 h1.2
  text "DIN" at -13.429,10.47 h1.2
  text "DIN" at 16.571,10.47 h1.2
  text "OE" at -13.379,8.805 h1.2
  text "GND" at 70.988,8 h1.5
  text "OE" at -88.429,7.93 h1.2
  text "OE" at 16.571,7.93 h1.2
  text "JDY_PWRC" at -25.825,7.39 h1.2
  text "VIN" at 71.001,6.513 h1.5
  text "RCK" at -88.429,5.39 h1.2
  text "RCK" at -13.429,5.39 h1.2
  text "RCK" at 16.571,5.39 h1.2
  text "U2_TX" at -23.814,5.317 h1.2
  text "*SHDN" at 70.989,5.024 h1.5
  text "GND" at 41.451,3.99 h1.2
  text "VIN" at 46.446,3.99 h1.2
  text "SCK" at -88.429,2.85 h1.2
  text "SCK" at -13.429,2.85 h1.2
  text "SCK" at 16.571,2.85 h1.2
  text "U2_RX" at -23.8,2.763 h1.2
  text "GND" at 42.931,1.777 h1.2
  text "VIN" at 47.981,1.777 h1.2
  text "5V" at -88.429,0.31 h1.2
  text "5V" at -13.429,0.31 h1.2
  text "5V" at 16.571,0.31 h1.2
  text "GND" at -88.429,-2.23 h1.2
  text "LD1" at 11.344,-4.596 h1.2
  text "LD1" at -52.632,-4.629 h1.2
  text "LD1" at -85.825,-4.65 h1.2
  text "LD2" at -61.944,-4.773 h1.2
  text "LD2" at -20.944,-4.773 h1.2
  text "LD2" at 43.056,-4.773 h1.2
  text "LD1" at 12.644,-7.121 h1.2
  text "LD2" at 43.063,-7.336 h1.2
  text "I2C" at -65.65,-9.3 h1.2
  text "SCL" at -65.65,-10.685 h1.2
  text "SDA" at -62.975,-10.685 h1.2
  text "GND" at -92.543,-14.456 h1.2
  text "No NET" at -58.543,-14.456 h1.2
  text "GND" at -51.543,-14.456 h1.2
  text "170V" at -17.543,-14.456 h1.2
  text "170V" at -17.543,-14.456 h1.2
  text "GND" at 12.457,-14.456 h1.2
  text "170V" at 46.457,-14.456 h1.2
  text "GND" at 53.457,-14.456 h1.2
  text "170V" at 87.457,-14.456 h1.2
  text "JDY_STAT" at -41.018,-18.24 h1.2
Bottom Overlay:
  drawing of 38 lines, arcs and shapes, not listed
  text "XP5    PROG" at -67.225,18.605 h1.2
  text "U1_RX" at -78.338,17.345 h1.2
  text "U1_TX" at -82.241,17.328 h1.2
  text "+3.3V" at -60.22,17.154 h1.2
  text "XP1" at -38.375,16.655 h1.2
  text "XP2" at -32.375,16.655 h1.2
  text "XP3" at -26.375,16.655 h1.2
  text "XP4" at -20.375,16.655 h1.2
  text "DM_LED1" at 11.377,16.065 h1.2
  text "BTN_1" at -38.375,15.33 h1.2
  text "BTN_2" at -32.375,15.33 h1.2
  text "BTN_3" at -26.375,15.33 h1.2
  text "BTN_4" at -20.375,15.33 h1.2
  text "DM_LED2" at 11.377,14.615 h1.2
  text "GND" at -87.451,12.595 h1.5
  text "VCC_5V" at -53.446,12.595 h1.5
  text "GND" at -46.451,12.595 h1.5
  text "VCC_5V" at -12.446,12.595 h1.5
  text "GND" at 17.549,12.595 h1.5
  text "VCC_5V" at 51.554,12.595 h1.5
  text "GND" at 58.549,12.595 h1.5
  text "VIN" at 92.554,12.595 h1.5
  text "DIN" at -86.3,10.47 h1.2
  text "DIN" at -11.3,10.47 h1.2
  text "DIN" at 18.7,10.47 h1.2
  text "OE" at -11.25,8.805 h1.2
  text "GND" at 74.514,7.979 h1.5
  text "OE" at -86.3,7.93 h1.2
  text "OE" at 18.7,7.93 h1.2
  text "JDY_PWRC" at -20.194,7.365 h1.2
  text "VIN" at 74.5,6.45 h1.5
  text "RCK" at -86.3,5.39 h1.2
  text "RCK" at -11.3,5.39 h1.2
  text "RCK" at 18.7,5.39 h1.2
  text "U2_TX" at -20.243,5.328 h1.2
  text "*SHDN" at 76.996,4.94 h1.5
  text "GND" at 46.549,3.595 h1.5
  text "VIN" at 51.554,3.595 h1.5
  text "SCK" at -86.3,2.85 h1.2
  text "SCK" at -11.3,2.85 h1.2
  text "SCK" at 18.7,2.85 h1.2
  text "U2_RX" at -20.256,2.755 h1.2
  text "GND" at 45.138,1.772 h1.2
  text "VIN" at 49.863,1.771 h1.2
  text "5V" at -86.3,0.31 h1.2
  text "5V" at -11.3,0.31 h1.2
  text "5V" at 18.7,0.31 h1.2
  text "GND" at -86.3,-2.23 h1.2
  text "LD1" at 13.256,-4.596 h1.2
  text "LD1" at -50.72,-4.627 h1.2
  text "LD1" at -83.953,-4.653 h1.2
  text "LD2" at -60.052,-4.771 h1.2
  text "LD2" at -19.056,-4.773 h1.2
  text "LD2" at 44.949,-4.784 h1.2
  text "LD1" at 14.506,-7.121 h1.2
  text "LD2" at 44.942,-7.332 h1.2
  text "I2C" at -57.336,-9.242 h1.2
  text "SCL" at -60.02,-10.641 h1.2
  text "SDA" at -57.35,-10.635 h1.2
  text "GND" at -87.457,-14.456 h1.5
  text "No NET" at -53.457,-14.456 h1.5
  text "GND" at -46.457,-14.456 h1.5
  text "170V" at -12.457,-14.456 h1.2
  text "GND" at 17.543,-14.456 h1.5
  text "170V" at 51.543,-14.456 h1.2
  text "GND" at 58.543,-14.456 h1.5
  text "170V" at 92.543,-14.456 h1.2
  text "JDY_STAT" at -35.432,-18.24 h1.2
Top Solder:
  region: -83.406,17.462 -83.407,17.462 -83.407,17.463 -83.406,17.463 -83.406,17.462 -83.404,17.462 -83.404,17.461 -83.406,17.461 -83.406,17.462
  region: -76.332,17.671 -76.331,17.671 -76.331,17.67 -76.332,17.67
  region: -76.331,17.669 -76.331,17.67 -76.33,17.67 -76.33,17.669
  region: -75.837,17.569 -75.837,17.57 -75.837,17.569 -75.836,17.569 -75.836,17.568 -75.837,17.568 -75.837,17.569
Mechanical 2:
  the board outline again, w0.254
